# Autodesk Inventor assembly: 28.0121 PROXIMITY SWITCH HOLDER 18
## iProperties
Created: 2007-05
Part Number: 28.0121 PROXIMITY SWITCH HOLDER 18
Document SubType Name: Assembly
Designer: Andy Moles
Author: Andy Moles
